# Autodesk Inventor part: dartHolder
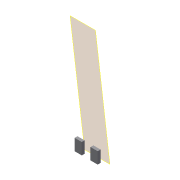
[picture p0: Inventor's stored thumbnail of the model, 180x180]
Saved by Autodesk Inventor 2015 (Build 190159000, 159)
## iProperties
Created: 2016-08
Part Number: dartHolder
Material: EIFS, Exterior Insulation
Document SubType Name: Modeling
Designer: user
Density: 0.023 g/cm^3
Appearance: Gray
Author: user
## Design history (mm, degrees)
sketch "Sketch1"
  geometry: L1 (25.4, -44.45)-(9.525, -44.45); L2 (9.525, -44.45)-(9.525, -19.05); L3 (9.525, -19.05)-(25.4, -19.05); L4 (25.4, -19.05)-(25.4, -44.45); L5 (-25.4, -44.45)-(-9.525, -44.45); L6 (-9.525, -44.45)-(-9.525, -19.05); L7 (-9.525, -19.05)-(-25.4, -19.05); L8 (-25.4, -19.05)-(-25.4, -44.45); 1 further point
  constraints: 16 end point, 4 parallel, 2 horizontal, 2 perpendicular
  dimensions: "d5" = 15.875 distance of L2.end L3.end; "d7" = 15.875 distance of L7.end L6.end
extrude "Extrusion1" new body sketch "Sketch1" distance "d3" = 6.35; taper "d4" = 0 deg
workplane "Work Plane1"
body "Solid1"
